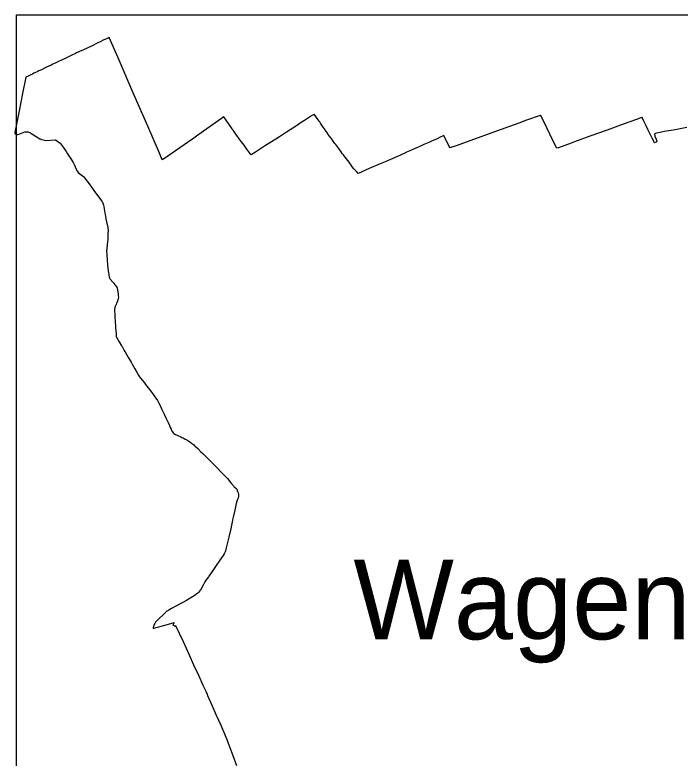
# Model space of a CAD drawing. Extents: x 113371 to 291721, y 393993 to 520143.
# Drawn here: x 169989 to 174170, y 441209 to 445881 of the extents above; entities that cross this region are included whole.
import ezdxf

# ---------------------------------------------------------------- set-up
doc = ezdxf.new("R2010")
doc.units = 0
for name, color, linetype in [('Boudingbox', 7, 'Continuous'), ('Default', 7, 'Continuous'), ('plaatsnamen', 7, 'Continuous'), ('vlieg gebied', 7, 'Continuous')]:
    doc.layers.add(name, color=color, linetype=linetype)

msp = doc.modelspace()

# ---------------------------------------------------------------- linework, layer by layer
at = {"layer": 'Boudingbox'}
msp.add_lwpolyline([(170000, 438680.149), (170000, 445881.46), (178185.135, 445881.46), (178185.135, 438680.149)], close=True, dxfattribs=at)
at = {"layer": 'Default'}
for points in [[(171299.305625, 445237.5925), (171288.005625, 445229.7525), (171287.295625, 445229.3125), (171140.025625, 445125.6125), (171105.005625, 445100.9325), (171101.375625, 445098.4125), (171025.615625, 445045.0025), (170923.605625, 444974.2025), (170922.895625, 444975.8825), (170915.925625, 444971.0525), (170898.815625, 445011.6625), (170824.505625, 445181.3225), (170739.365625, 445377.0425), (170718.425625, 445425.1725), (170637.795625, 445611.8025), (170582.785625, 445738.9225), (170575.505625, 445735.5825), (170570.585625, 445733.3525), (170549.035625, 445723.7125), (170525.845625, 445712.7925), (170511.575625, 445705.8025), (170505.895625, 445703.1825), (170474.285625, 445687.6025), (170416.625625, 445660.0625), (170409.785625, 445657.5125), (170377.175625, 445642.3325), (170370.575625, 445639.1525), (170343.895625, 445626.2725), (170310.095625, 445609.8525), (170306.225625, 445608.0025), (170305.565625, 445607.6525), (170301.555625, 445605.5025), (170300.765625, 445604.8725), (170297.135625, 445603.0325), (170290.035625, 445600.1125), (170256.005625, 445584.2825), (170238.005625, 445575.6625), (170226.905625, 445570.5125)], [(170226.905625, 445570.5125), (170217.835625, 445565.5725), (170188.805625, 445551.8425), (170152.215625, 445534.3425), (170139.425625, 445528.6225), (170133.785625, 445526.4325), (170115.695625, 445517.7525), (170109.195625, 445514.4825), (170099.515625, 445509.6525), (170090.425625, 445505.2125), (170089.305625, 445504.6325), (170076.115625, 445498.4325), (170068.635625, 445494.8625), (170061.795625, 445491.6225), (170061.635625, 445491.5425), (170057.515625, 445489.5125), (170037.665625, 445387.4925), (170016.575625, 445279.1725), (169989.975625, 445141.7725), (169989.925625, 445141.5425), (169989.325625, 445140.9625), (169990.025625, 445137.3725), (170002.635625, 445126.8625), (170020.855625, 445132.7825), (170040.555625, 445141.5125), (170051.815625, 445146.3925), (170073.575625, 445145.1725), (170087.145625, 445139.3325), (170089.705625, 445137.8025), (170122.475625, 445115.9225), (170146.585625, 445102.3825), (170147.825625, 445101.6925), (170153.225625, 445099.3425), (170156.015625, 445098.1325), (170166.515625, 445094.8425), (170182.895625, 445092.3325), (170245.275625, 445095.6625), (170274.445625, 445075.0825)], [(171894.585625, 445222.4425), (171884.285625, 445236.6325), (171880.675625, 445241.5025), (171875.925625, 445248.3525), (171870.365625, 445256.4925), (171869.415625, 445255.9625), (171856.705625, 445248.8125), (171852.395625, 445246.0925), (171849.015625, 445243.9525), (171847.465625, 445242.9625), (171816.185625, 445222.3425), (171809.615625, 445218.0425), (171788.695625, 445204.3325), (171758.205625, 445184.3425), (171695.425625, 445143.5025), (171652.065625, 445115.6025), (171629.255625, 445100.9225), (171565.325625, 445059.2325), (171500.695625, 445017.7525), (171473.925625, 445000.5825), (171472.385625, 445003.3725), (171470.745625, 445005.4425), (171461.385625, 445017.7525), (171458.855625, 445021.0725), (171447.085625, 445037.2825), (171429.305625, 445061.3025), (171413.925625, 445082.3225), (171411.185625, 445085.3925), (171399.675625, 445101.7825), (171384.675625, 445122.9725), (171369.145625, 445144.8125), (171360.815625, 445156.8025), (171359.665625, 445158.5225), (171357.885625, 445161.0625), (171354.645625, 445165.9225), (171316.765625, 445218.9525), (171302.305625, 445239.6725), (171299.305625, 445237.5925)], [(173994.725625, 445105.9025), (173984.565625, 445126.2625), (173969.235625, 445156.9625), (173957.745625, 445180.4325), (173950.135625, 445196.0225), (173947.425625, 445201.6325), (173941.865625, 445213.2925), (173930.545625, 445235.9725), (173930.285625, 445236.2125), (173929.985625, 445236.3325), (173929.675625, 445236.3625), (173929.355625, 445236.2725), (173922.405625, 445233.3925), (173910.255625, 445229.1125), (173901.705625, 445226.0925), (173842.335625, 445205.1625), (173779.525625, 445182.3425), (173711.205625, 445157.6325), (173609.265625, 445120.5125), (173505.675625, 445082.8225), (173484.865625, 445075.1025), (173406.425625, 445045.9625), (173405.265625, 445045.6225), (173403.525625, 445045.1125), (173395.815625, 445042.8225), (173370.025625, 445091.7725), (173332.045625, 445170.3325), (173293.945625, 445248.7225), (173293.255625, 445250.1625), (173291.435625, 445249.4725), (173205.245625, 445218.5425), (173157.035625, 445201.3025), (173015.705625, 445150.4525), (172756.695625, 445057.0925), (172735.205625, 445049.1125), (172734.235625, 445048.7625), (172729.555625, 445047.0225), (172723.345625, 445044.8525)], [(172111.785625, 444923.9525), (172106.395625, 444931.2725), (172094.005625, 444948.1825), (172084.105625, 444963.2125), (172081.735625, 444966.2825), (172065.775625, 444986.6125), (172054.715625, 445000.6325), (172054.585625, 445000.7925), (172046.565625, 445010.9625), (172042.235625, 445016.2825), (172041.645625, 445017.1425), (172041.575625, 445017.2525), (172041.225625, 445017.7525), (172033.925625, 445028.4325), (172024.285625, 445042.0825), (172024.245625, 445042.1425), (172018.555625, 445050.2825), (172005.905625, 445065.6525), (172000.215625, 445073.0025), (171993.675625, 445081.7225), (171984.445625, 445094.0825), (171980.615625, 445099.3125), (171974.445625, 445107.6725), (171966.105625, 445119.0425), (171956.335625, 445132.5125), (171953.275625, 445137.1925), (171949.295625, 445143.3025), (171945.925625, 445147.6825), (171934.735625, 445164.6525), (171932.975625, 445167.6525), (171931.685625, 445169.5225), (171914.965625, 445193.8925), (171914.905625, 445193.9825), (171910.585625, 445200.2725), (171904.985625, 445208.3225), (171902.175625, 445212.3525), (171894.645625, 445222.3525), (171894.585625, 445222.4425)], [(174211.975625, 445172.5225), (174159.415625, 445162.6125), (174114.475625, 445153.9325), (174070.305625, 445147.3225), (174044.465625, 445141.6225), (174021.105625, 445136.7925), (174008.325625, 445134.1425), (174010.325625, 445118.6325), (174018.855625, 445101.0925), (174022.175625, 445094.3425), (174022.495625, 445093.4925), (174022.735625, 445092.6125), (174022.905625, 445091.7225), (174022.985625, 445090.8125), (174022.995625, 445089.9025), (174022.925625, 445088.9925), (174022.775625, 445088.1025), (174022.555625, 445087.2225), (174022.255625, 445086.3625), (174021.875625, 445085.5325), (174021.425625, 445084.7425), (174020.915625, 445083.9925), (174020.335625, 445083.2825), (174019.705625, 445082.6325), (174019.015625, 445082.0425), (174008.385625, 445077.0325), (174008.255625, 445077.5625), (174007.615625, 445080.0925), (174001.765625, 445092.4325), (173994.725625, 445105.9025)], [(172723.345625, 445044.8525), (172721.435625, 445048.6425), (172721.275625, 445048.9625), (172717.685625, 445056.1425), (172710.605625, 445070.3825), (172703.275625, 445084.9925), (172700.485625, 445090.5125), (172697.515625, 445096.5025), (172685.375625, 445122.5825), (172681.835625, 445120.9325), (172661.945625, 445111.6725), (172642.555625, 445102.6425), (172618.605625, 445092.0925), (172612.295625, 445089.3125), (172590.355625, 445079.6525), (172558.885625, 445066.6325), (172538.445625, 445056.9525), (172533.425625, 445054.3625), (172523.485625, 445050.0425), (172489.965625, 445036.0125), (172472.215625, 445027.6525), (172449.775625, 445017.7525), (172448.645625, 445017.2525), (172443.565625, 445013.8725), (172413.125625, 445000.2425), (172316.195625, 444958.4425), (172285.305625, 444945.1925), (172215.495625, 444914.8825), (172165.815625, 444892.7625), (172162.835625, 444891.4325), (172157.815625, 444889.0225), (172156.745625, 444888.5225), (172156.175625, 444888.2325), (172155.675625, 444888.0225), (172146.595625, 444883.7825), (172140.255625, 444891.8525), (172118.945625, 444914.2125), (172111.785625, 444923.9525)], [(170274.445625, 445075.0825), (170292.465625, 445050.7225), (170311.425625, 445021.9125), (170320.925625, 445007.3225), (170340.625625, 444977.0525), (170355.225625, 444952.8325), (170364.195625, 444936.5125), (170367.965625, 444926.1225), (170368.555625, 444924.5225), (170378.025625, 444905.1425), (170381.615625, 444898.2625), (170389.305625, 444888.3225), (170423.095625, 444862.3625), (170428.985625, 444854.9725), (170432.975625, 444849.5925), (170449.955625, 444826.7225), (170476.225625, 444790.9325), (170490.205625, 444771.8825), (170505.055625, 444751.5025), (170520.815625, 444729.3825), (170535.065625, 444709.3825), (170535.585625, 444708.6525), (170539.385625, 444703.3225), (170545.785625, 444685.2125), (170547.585625, 444677.5625), (170550.405625, 444662.7625), (170556.825625, 444624.9825), (170558.355625, 444616.9025), (170561.695625, 444599.2125), (170572.735625, 444545.6225), (170573.755625, 444540.2625), (170575.185625, 444530.2325), (170574.985625, 444521.6325), (170574.785625, 444517.7525), (170574.715625, 444516.3825), (170574.485625, 444511.5425), (170572.505625, 444471.8325), (170569.715625, 444435.0625)], [(170569.715625, 444435.0625), (170567.925625, 444413.6125), (170566.145625, 444393.6925), (170566.665625, 444379.6525), (170567.035625, 444374.0525), (170567.155625, 444372.2825), (170569.245625, 444340.5925), (170571.265625, 444307.0625), (170571.305625, 444306.3925), (170572.845625, 444290.8225), (170575.055625, 444272.8025), (170576.805625, 444261.4025), (170579.525625, 444248.4525), (170580.295625, 444245.0325), (170582.855625, 444233.6525), (170584.145625, 444228.8025), (170588.495625, 444220.6425), (170605.705625, 444200.4525), (170611.295625, 444193.8925), (170618.205625, 444185.2325), (170623.845625, 444178.0925), (170631.775625, 444166.1125), (170634.615625, 444150.0425), (170638.455625, 444128.3425), (170639.025625, 444117.8725), (170639.745625, 444104.6025), (170638.985625, 444097.1925), (170631.275625, 444075.5925), (170631.055625, 444075.2825), (170630.255625, 444074.1525), (170629.985625, 444073.7225), (170627.285625, 444069.3425), (170627.005625, 444068.3225), (170625.115625, 444061.5525), (170619.985625, 444048.6725), (170618.495625, 444041.2325), (170616.105625, 444027.9525), (170615.875625, 444019.3725)], [(170615.875625, 444019.3725), (170617.245625, 444001.0625), (170618.325625, 443984.8925), (170620.545625, 443952.0525), (170622.025625, 443926.2525), (170622.695625, 443914.7025), (170623.725625, 443896.8725), (170624.975625, 443875.0025), (170625.655625, 443865.3425), (170626.455625, 443860.0825), (170627.705625, 443855.1625), (170629.305625, 443851.8525), (170635.855625, 443841.4125), (170644.935625, 443826.9425), (170659.955625, 443801.7425), (170663.335625, 443796.0525), (170668.535625, 443787.3425), (170677.235625, 443771.9825), (170686.765625, 443755.1625), (170695.535625, 443739.9925), (170704.225625, 443724.9925), (170719.875625, 443697.2625), (170723.935625, 443690.0825), (170742.875625, 443656.3725), (170757.335625, 443630.9525), (170759.275625, 443627.5425), (170767.835625, 443612.4425), (170771.825625, 443606.5025), (170779.245625, 443597.3625), (170802.945625, 443568.2025), (170811.055625, 443558.2325), (170836.045625, 443525.7925), (170857.005625, 443498.2025), (170869.895625, 443481.0725), (170876.125625, 443471.4425), (170884.795625, 443457.5025), (170894.035625, 443440.8125), (170903.855625, 443422.4125)], [(170903.855625, 443422.4125), (170913.895625, 443401.3825), (170928.465625, 443371.5125), (170941.025625, 443343.6125), (170951.725625, 443319.5525), (170961.195625, 443299.2025), (170965.975625, 443288.2625), (170970.545625, 443277.8225), (170974.645625, 443268.1525), (170979.095625, 443260.4925), (170984.225625, 443254.5525), (170989.245625, 443249.6425), (170997.805625, 443244.2825), (171013.925625, 443236.4125), (171032.045625, 443228.4525), (171039.165625, 443225.3325), (171046.015625, 443222.1425), (171060.075625, 443214.6125), (171061.535625, 443213.8225), (171076.595625, 443205.0425), (171089.605625, 443196.7225), (171099.655625, 443189.3025), (171110.945625, 443179.9425), (171119.105625, 443173.1425), (171120.015625, 443172.3425), (171124.695625, 443168.2325), (171138.395625, 443154.9925), (171156.425625, 443137.0625), (171169.745625, 443123.9325), (171186.725625, 443107.2025), (171214.915625, 443078.9925), (171220.905625, 443073.0225), (171256.515625, 443037.5025), (171290.945625, 443002.8225), (171310.885625, 442982.4325), (171324.685625, 442965.9825), (171346.595625, 442939.9425), (171362.875625, 442920.7125)], [(171362.875625, 442920.7125), (171365.975625, 442916.8825), (171367.145625, 442915.4425), (171367.325625, 442915.2225), (171377.255625, 442905.6325), (171385.755625, 442896.7225), (171386.845625, 442895.5725), (171386.785625, 442894.8525), (171386.605625, 442892.8425), (171386.725625, 442890.0925), (171387.295625, 442887.3425), (171389.805625, 442882.2025), (171393.455625, 442875.3425), (171394.235625, 442870.4925), (171394.125625, 442869.6925), (171394.695625, 442861.0025), (171394.465625, 442853.5625), (171392.865625, 442845.6625), (171390.015625, 442838.4425), (171386.365625, 442829.8525), (171384.645625, 442824.8125), (171380.885625, 442808.9025), (171376.665625, 442789.7225), (171371.525625, 442768.7725), (171361.145625, 442723.0525), (171357.565625, 442706.8725), (171354.175625, 442691.5625), (171350.505625, 442673.4625), (171345.845625, 442650.5525), (171340.485625, 442624.1125), (171338.675625, 442616.1725), (171334.335625, 442598.0825), (171325.425625, 442564.1925), (171317.105625, 442531.1825), (171312.545625, 442512.6325), (171310.715625, 442506.5625), (171307.405625, 442497.5125), (171305.125625, 442492.3625)], [(171305.125625, 442492.3625), (171297.935625, 442481.8125), (171277.755625, 442452.7625), (171254.825625, 442419.6425), (171228.505625, 442381.9025), (171207.935625, 442351.9325), (171206.245625, 442349.4725), (171192.125625, 442329.3625), (171183.795625, 442317.7825), (171174.895625, 442300.8325), (171155.855625, 442265.5925), (171154.715625, 442264.1825), (171150.485625, 442258.9425), (171143.525625, 442251.0325), (171142.895625, 442250.3625), (171138.795625, 442246.0525), (171133.425625, 442241.2325), (171123.385625, 442234.4625), (171105.235625, 442222.9825), (171084.815625, 442210.2325), (171067.695625, 442200.8125), (171040.845625, 442185.9225), (171004.195625, 442165.8125), (170973.105625, 442148.6225), (170957.815625, 442140.1125), (170949.935625, 442135.7525), (170944.805625, 442132.6525), (170940.925625, 442130.1225), (170937.615625, 442127.0225), (170922.775625, 442112.6925), (170894.615625, 442085.0025), (170879.115625, 442069.9925), (170872.615625, 442062.7725), (170868.055625, 442055.2125), (170863.485625, 442045.0125), (170860.755625, 442036.6825), (170858.815625, 442029.5825), (170858.135625, 442024.6625)], [(170858.135625, 442024.6625), (170858.965625, 442024.8825), (170877.875625, 442029.9725), (170925.695625, 442043.0025), (170990.585625, 442061.2125), (170982.825625, 442044.4925), (170990.125625, 442041.9925), (170990.645625, 442040.3025), (170995.885625, 442041.7025), (170997.495625, 442042.1425), (170999.595625, 442042.7025), (171046.005625, 441941.1725), (171083.785625, 441858.5425), (171112.505625, 441796.2325), (171142.395625, 441730.9525), (171170.915625, 441668.4325), (171190.625625, 441625.5925), (171192.275625, 441621.6725), (171196.815625, 441610.8925), (171200.435625, 441602.3025), (171227.585625, 441541.5625), (171255.105625, 441479.4525), (171282.985625, 441416.3825), (171317.335625, 441337.1725), (171334.625625, 441293.1325), (171358.925625, 441226.3925), (171381.295625, 441162.7925)]]:
    msp.add_lwpolyline(points, dxfattribs=at)
at = {"layer": 'vlieg gebied'}
msp.add_lwpolyline([(170000, 438680.149), (170000, 445881.46), (178185.135, 445881.46), (178185.135, 438680.149)], close=True, dxfattribs=at)

# ---------------------------------------------------------------- texts
at = {"layer": 'plaatsnamen'}
msp.add_text('Wageningen', height=500, dxfattribs=at).set_placement((172117.282092, 441956.169256))

doc.saveas('drawing.dxf')
